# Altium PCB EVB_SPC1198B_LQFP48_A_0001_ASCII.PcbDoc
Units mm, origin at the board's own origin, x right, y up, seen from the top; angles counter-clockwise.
Board outline 65.1 x 66.6 mm, 2 copper layers (Top Layer, Bottom Layer); 51 components, 65 nets, 202 pads, 46 vias.
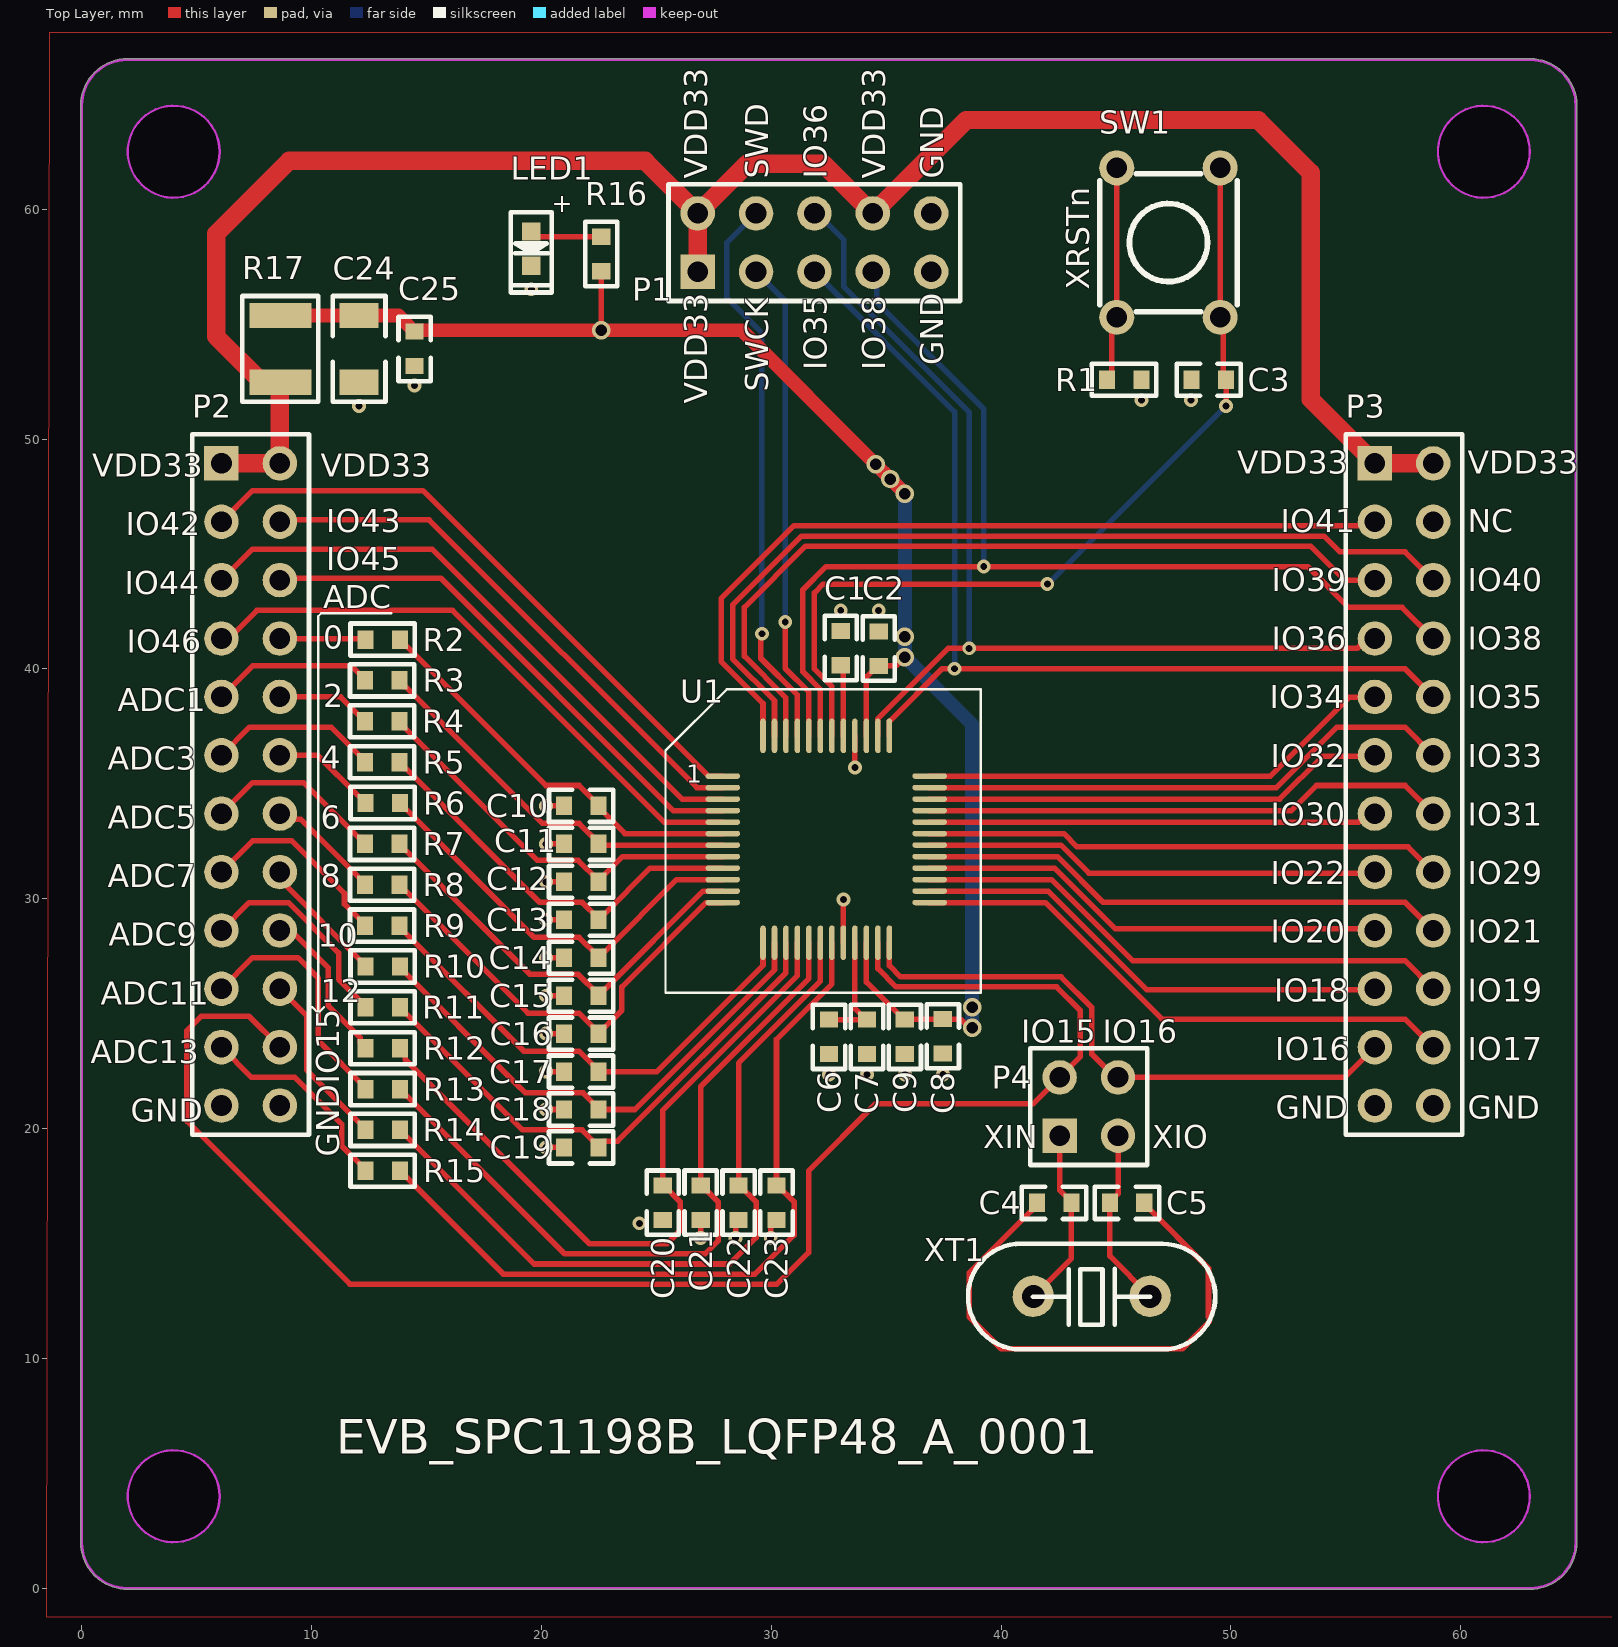
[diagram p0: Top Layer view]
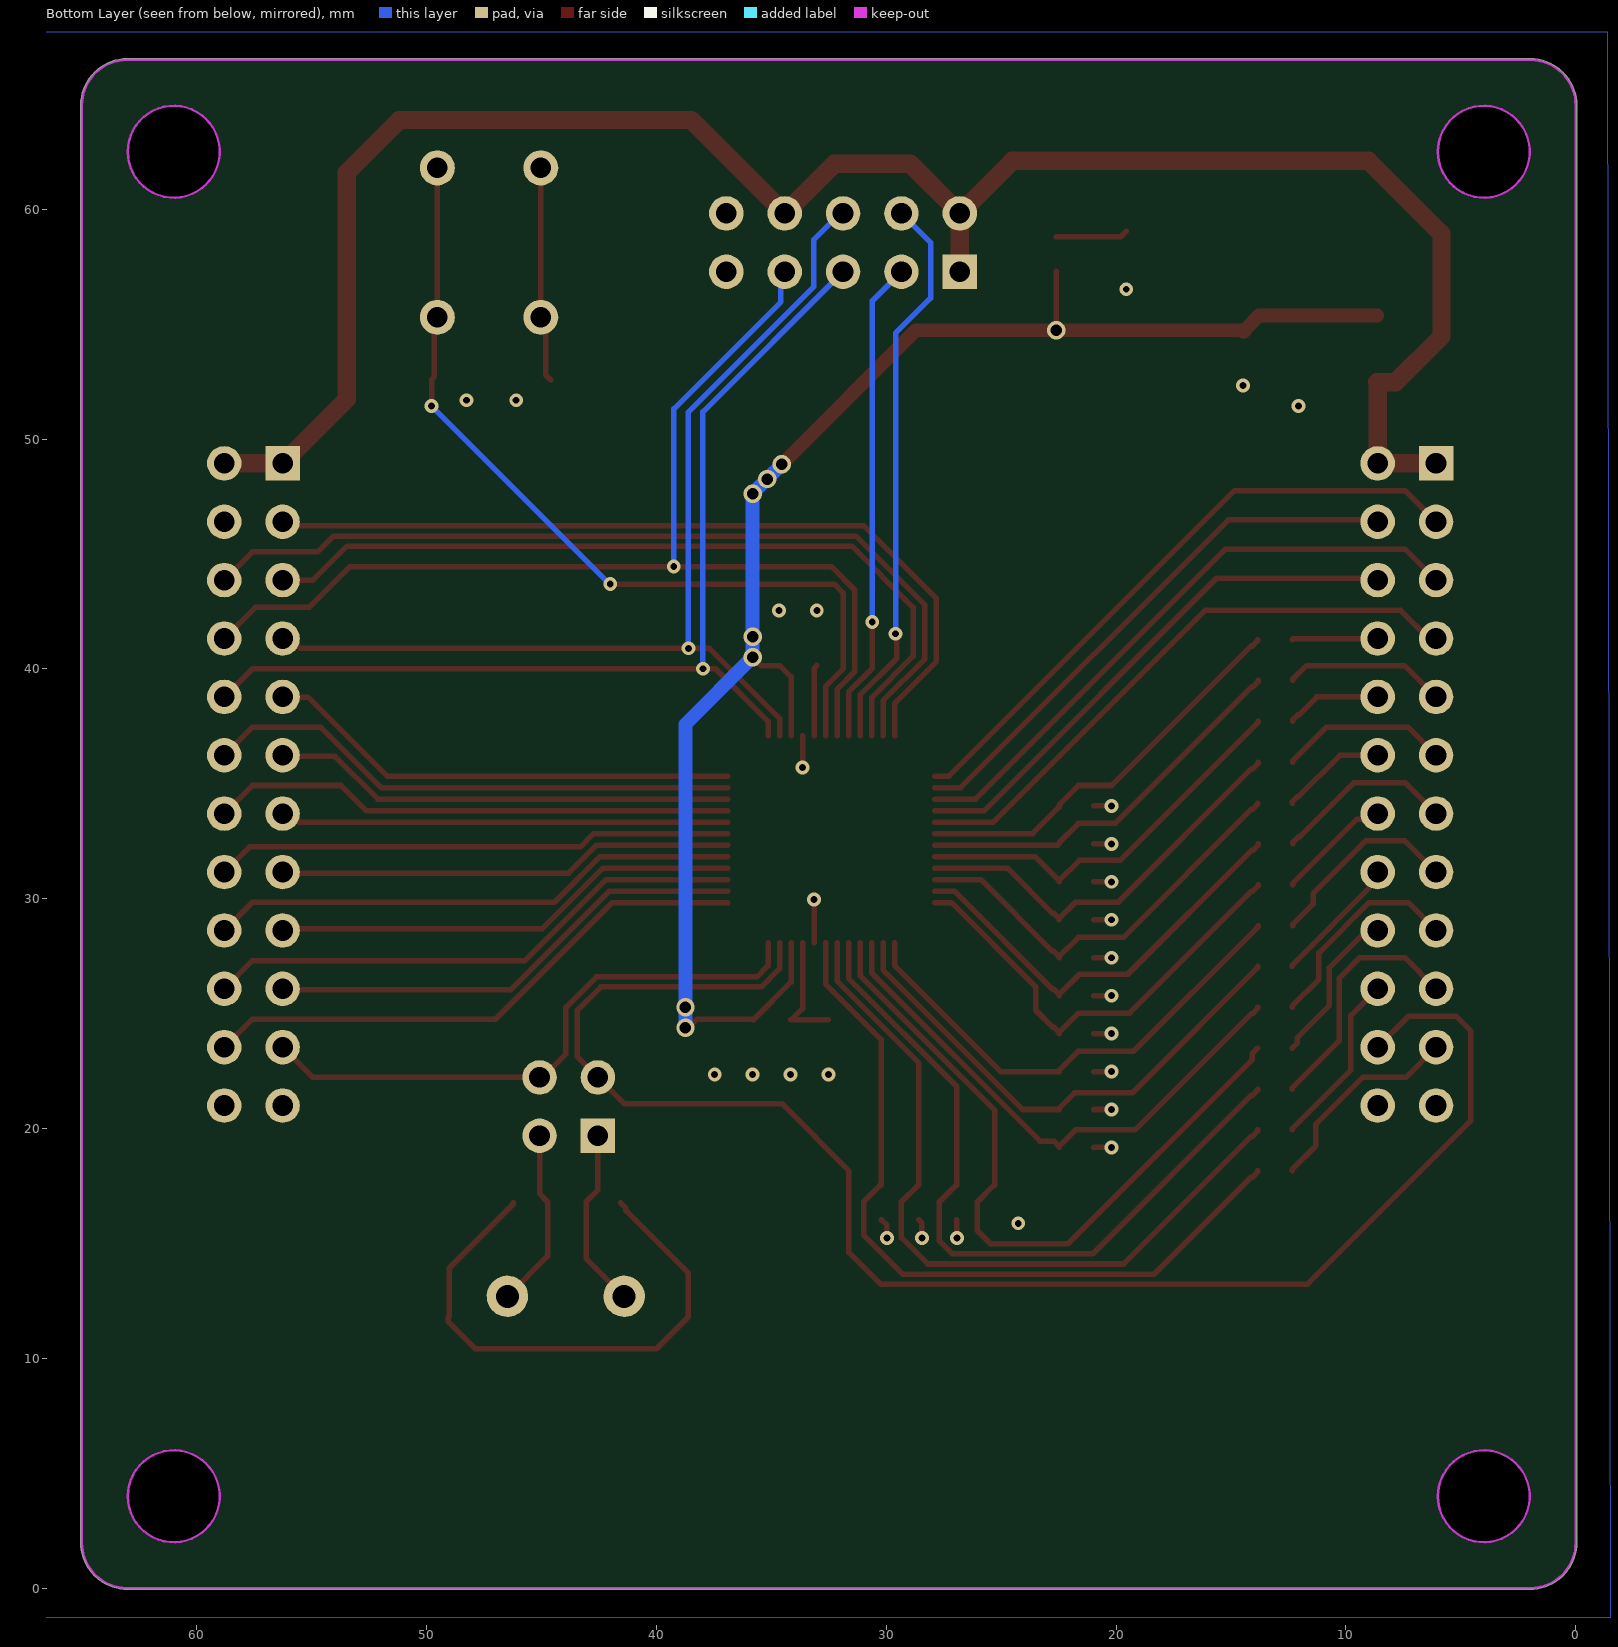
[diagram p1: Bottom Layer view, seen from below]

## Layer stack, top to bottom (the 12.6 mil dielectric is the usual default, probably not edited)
Top Solder: solder mask 0.0102, Solder Resist, Dk 3.5
Top Layer: signal copper 0.0356
Dielectric 1: dielectric 0.32, FR-4, Dk 4.8
Bottom Layer: signal copper 0.0356
Bottom Solder: solder mask 0.0102, Solder Resist, Dk 3.5

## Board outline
-0.05,2 cw(c0,2) -0.048,2.016 cw(c0,2.032) -0.05,2.032 -0.05,64.516 cw(c0,64.516) -0.05,64.519 cw(c2,64.5) 1.981,66.55 cw(c1.984,66.5) 1.984,66.55 63.04,66.55 cw(c63.04,66.5) 63.047,66.55 cw(c63,64.5) 65.05,64.547 cw(c65,64.54) 65.05,64.54 65.05,2.008 cw(c65,2.008) 65.05,2.004 cw(c65,2) 65.05,2 cw(c63,2) 63,-0.05 cw(c63,0) 62.996,-0.05 cw(c62.992,0) 62.992,-0.05 2.032,-0.05 cw(c2.032,0) 2.016,-0.048 cw(c2,0) 2,-0.05 cw(c2,2)

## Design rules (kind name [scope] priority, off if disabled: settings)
AssemblyTestPointUsage [All] p0: scope1count=1 scope1_0_kind=Board scope1_0_value=Board scope2count=1 scope2_0_kind=Board scope2_0_value=Board commentlength=0
AssemblyTestpoint [All] p0: scope1count=1 scope1_0_kind=Board scope1_0_value=Board scope2count=1 scope2_0_kind=Board scope2_0_value=Board commentlength=0
Clearance [All] p0: scope1count=1 scope1_0_kind=Board scope1_0_value=Board scope2count=1 scope2_0_kind=Board scope2_0_value=Board commentlength=0 gap=0.2
Clearance [All] p1: gap=0.2 ignorepadtopadclearanceinfootprint=FALSE except(0: Arc-Hole Track-Hole SMDPad-Hole THPad-Hole Via-Hole Fill-Hole Poly-Hole Region-Hole Text-Hole)
ComponentClearance [All] p0: scope1count=1 scope1_0_kind=Board scope1_0_value=Board scope2count=1 scope2_0_kind=Board scope2_0_value=Board commentlength=0 gap=0.254 collisioncheckmode=3
DiffPairsRouting [All] p0: scope1count=1 scope1_0_kind=Board scope1_0_value=Board scope2count=1 scope2_0_kind=Board scope2_0_value=Board commentlength=0
FabricationTestPointUsage [All] p0: scope1count=1 scope1_0_kind=Board scope1_0_value=Board scope2count=1 scope2_0_kind=Board scope2_0_value=Board commentlength=0 valid=0 allowmultiple=FALSE
FabricationTestpoint [All] p0: scope1count=1 scope1_0_kind=Board scope1_0_value=Board scope2count=1 scope2_0_kind=Board scope2_0_value=Board commentlength=0 side=3 testpointundercomponent=TRUE minsize=1.016 maxsize=2.54 preferedsize=1.524 minholesize=0 maxholesize=1.016 preferedholesize=0.813 testpointgrid=0.025
FanoutControl Fanout_BGA [All] p0 off: scope1count=1 scope1_0_kind=Board scope1_0_value=Board scope2count=1 scope2_0_kind=Board scope2_0_value=Board commentlength=69 // Protel DXP Scope 1 Expression Was: IsBGA   Fanout_BGA (Default Rule)
FanoutControl Fanout_LCC [All] p0 off: scope1count=1 scope1_0_kind=Board scope1_0_value=Board scope2count=1 scope2_0_kind=Board scope2_0_value=Board commentlength=69 // Protel DXP Scope 1 Expression Was: IsLCC   Fanout_LCC (Default Rule)
FanoutControl Fanout_SOIC [All] p0 off: scope1count=1 scope1_0_kind=Board scope1_0_value=Board scope2count=1 scope2_0_kind=Board scope2_0_value=Board commentlength=71 // Protel DXP Scope 1 Expression Was: IsSOIC   Fanout_SOIC (Default Rule)
FanoutControl Fanout_Small [All] p0 off: scope1count=1 scope1_0_kind=Board scope1_0_value=Board scope2count=1 scope2_0_kind=Board scope2_0_value=Board commentlength=84 // Protel DXP Scope 1 Expression Was: (CompPinCount < 5)   Fanout_Small (Default Rule)
FanoutControl Fanout_Default [All] p0: scope1count=1 scope1_0_kind=Board scope1_0_value=Board scope2count=1 scope2_0_kind=Board scope2_0_value=Board commentlength=30 // Fanout_Default (Default Rule)
Height [All] p0: scope1count=1 scope1_0_kind=Board scope1_0_value=Board scope2count=1 scope2_0_kind=Board scope2_0_value=Board commentlength=0
HoleSize [All] p0: scope1count=1 scope1_0_kind=Board scope1_0_value=Board scope2count=1 scope2_0_kind=Board scope2_0_value=Board commentlength=0 absolutevalues=TRUE maxlimit=2.54 minlimit=0.025 maxpercent=80.000 minpercent=20.000
HoleToHoleClearance [All] p0: scope1count=1 scope1_0_kind=Board scope1_0_value=Board scope2count=1 scope2_0_kind=Board scope2_0_value=Board commentlength=0
LayerPairs [All] p0: scope1count=1 scope1_0_kind=Board scope1_0_value=Board scope2count=1 scope2_0_kind=Board scope2_0_value=Board commentlength=0 enforce=TRUE
MinimumSolderMaskSliver [All] p0: scope1count=1 scope1_0_kind=Board scope1_0_value=Board scope2count=1 scope2_0_kind=Board scope2_0_value=Board commentlength=0
NetAntennae [All] p0: scope1count=1 scope1_0_kind=Board scope1_0_value=Board scope2count=1 scope2_0_kind=Board scope2_0_value=Board commentlength=0
PasteMaskExpansion [All] p0: scope1count=1 scope1_0_kind=Board scope1_0_value=Board scope2count=1 scope2_0_kind=Board scope2_0_value=Board commentlength=0 expansion=0
PlaneClearance [All] p0: scope1count=1 scope1_0_kind=Board scope1_0_value=Board scope2count=1 scope2_0_kind=Board scope2_0_value=Board commentlength=0 clearance=0.508
PlaneConnect [All] p0: scope1count=1 scope1_0_kind=Board scope1_0_value=Board scope2count=1 scope2_0_kind=Board scope2_0_value=Board commentlength=0 planeconnectstyle=Direct reliefexpansion=0.508 reliefentries=4 reliefconductorwidth=0.254 reliefairgap=0.254
PlaneConnect [All] p1: planeconnectstyle=Direct reliefexpansion=0.508 reliefentries=4 reliefconductorwidth=0.254 reliefairgap=0.254
PolygonConnect [All] p0: scope1count=1 scope1_0_kind=Board scope1_0_value=Board scope2count=1 scope2_0_kind=Board scope2_0_value=Board commentlength=0 connectstyle=Direct reliefconductorwidth=0.254 reliefentries=4 polygonreliefangle="90 Angle"
PolygonConnect [All] p1: connectstyle=Direct reliefconductorwidth=0.254 reliefentries=4 polygonreliefangle="90 Angle" airgapwidth=0.254
RoutingCorners [All] p0: scope1count=1 scope1_0_kind=Board scope1_0_value=Board scope2count=1 scope2_0_kind=Board scope2_0_value=Board commentlength=0 cornerstyle=45-Degree minsetback=2.54 maxsetback=2.54
RoutingLayers [All] p0: scope1count=1 scope1_0_kind=Board scope1_0_value=Board scope2count=1 scope2_0_kind=Board scope2_0_value=Board commentlength=0 top layer=Automatic bottom layer=Automatic
RoutingPriority [All] p0: scope1count=1 scope1_0_kind=Board scope1_0_value=Board scope2count=1 scope2_0_kind=Board scope2_0_value=Board commentlength=0
RoutingTopology [All] p0: scope1count=1 scope1_0_kind=Board scope1_0_value=Board scope2count=1 scope2_0_kind=Board scope2_0_value=Board commentlength=0 topology=Shortest
RoutingVias [All] p0: scope1count=1 scope1_0_kind=Board scope1_0_value=Board scope2count=1 scope2_0_kind=Board scope2_0_value=Board commentlength=0 holewidth=0.711 width=1.27 viastyle="Through Hole" minholewidth=0.711 minwidth=1.27 maxholewidth=0.711 maxwidth=1.27
RoutingVias [All] p1: holewidth=0.711 width=1.27 viastyle="Through Hole" minholewidth=0.711 minwidth=1.27 maxholewidth=0.711 maxwidth=1.27
ShortCircuit [All] p0: scope1count=1 scope1_0_kind=Board scope1_0_value=Board scope2count=1 scope2_0_kind=Board scope2_0_value=Board commentlength=0 allowed=FALSE
SilkToBoardRegionClearance [All] p0: scope1count=1 scope1_0_kind=Board scope1_0_value=Board scope2count=1 scope2_0_kind=Board scope2_0_value=Board commentlength=0
SilkToSilkClearance [All] p0: scope1count=1 scope1_0_kind=Board scope1_0_value=Board scope2count=1 scope2_0_kind=Board scope2_0_value=Board commentlength=0
SilkToSolderMaskClearance [All] p0 off: scope1count=1 scope1_0_kind=Board scope1_0_value=Board scope2count=1 scope2_0_kind=Board scope2_0_value=Board commentlength=44 // Protel DXP Scope 1 Expression Was: IsPad
SolderMaskExpansion [All] p0: scope1count=1 scope1_0_kind=Board scope1_0_value=Board scope2count=1 scope2_0_kind=Board scope2_0_value=Board commentlength=0 expansion=0.102
SolderMaskExpansion [All] p1: expansion=0.102 istentingtop=FALSE
UnRoutedNet [All] p0: scope1count=1 scope1_0_kind=Board scope1_0_value=Board scope2count=1 scope2_0_kind=Board scope2_0_value=Board commentlength=0
UnpouredPolygon [All] p0: scope1count=1 scope1_0_kind=Board scope1_0_value=Board scope2count=1 scope2_0_kind=Board scope2_0_value=Board commentlength=0
Width [All] p0: scope1count=1 scope1_0_kind=Board scope1_0_value=Board scope2count=1 scope2_0_kind=Board scope2_0_value=Board commentlength=0 maxlimit=4 minlimit=0.15 preferedwidth=0.254
Width [All] p1: maxlimit=4 minlimit=0.15 preferedwidth=0.254 minimp=50.000000 maximp=50.000000 favimp=50.000000
29 further rules are at their usual default settings.

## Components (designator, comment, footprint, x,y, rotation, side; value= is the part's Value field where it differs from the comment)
C1 "100nF" 0603C 33.02,40.156 r90 top
C2 "100nF" 0603C 34.671,41.632 r270 top
C3 "100nF" 0603C 48.284,52.578 r0 top
C4 "20pF" 0603C 41.553,16.764 r0 top
C5 "20pF" 0603C 46.228,16.764 r180 top
C6 "2.2uF" 0603C 32.512,23.241 r90 top
C7 "100nF" 0603C 34.163,23.241 r90 top
C8 "2.2uF" 0603C 37.465,23.265 r90 top
C9 "100nF" 0603C 35.814,23.241 r90 top
C10 "100pF" 0603C 22.479,34.036 r180 top
C11 "100pF" 0603C 22.479,32.385 r180 top
C12 "100pF" 0603C 22.479,30.734 r180 top
C13 "100pF" 0603C 22.479,29.083 r180 top
C14 "100pF" 0603C 22.479,27.432 r180 top
C15 "100pF" 0603C 22.479,25.781 r180 top
C16 "100pF" 0603C 22.479,24.13 r180 top
C17 "100pF" 0603C 22.479,22.479 r180 top
C18 "100pF" 0603C 22.479,20.828 r180 top
C19 "100pF" 0603C 22.479,19.177 r180 top
C20 "100pF" 0603C 25.273,17.526 r270 top
C21 "100pF" 0603C 26.924,17.526 r270 top
C22 "100pF" 0603C 28.575,17.526 r270 top
C23 "100pF" 0603C 30.226,17.526 r270 top
C24 "47uF" 1206C 12.065,52.472 r90 top
C25 "100nF" 0603C 14.478,53.172 r90 top
LED1 "" LED0603 19.558,59.031 r270 top
P1 "Header 5X2" HDR2X5 26.797,57.277 r0 top
P2 "Header 12X2" HDR2X12 6.077,48.94 r270 top locked
P3 "Header 12X2" HDR2X12 56.261,48.94 r270 top locked
P4 "Header 2X2" HDR2X2 42.545,19.685 r0 top
R1 "2K" 0603R 44.601,52.578 r0 top
R2 "100R" 0603R 13.843,41.275 r180 top
R3 "100R" 0603R 13.819,39.497 r180 top
R4 "100R" 0603R 13.819,37.719 r180 top
R5 "100R" 0603R 13.819,35.941 r180 top
R6 "100R" 0603R 13.843,34.163 r180 top
R7 "100R" 0603R 13.819,32.385 r180 top
R8 "100R" 0603R 13.819,30.607 r180 top
R9 "100R" 0603R 13.819,28.829 r180 top
R10 "100R" 0603R 13.843,27.051 r180 top
R11 "100R" 0603R 13.843,25.273 r180 top
R12 "100R" 0603R 13.843,23.495 r180 top
R13 "100R" 0603R 13.843,21.717 r180 top
R14 "100R" 0603R 13.843,19.939 r180 top
R15 "100R" 0603R 13.843,18.161 r180 top
R16 "3.3K" 0603R 22.606,57.301 r90 top
R17 "0.1R" 1210R 8.636,55.372 r270 top
SW1 "插件按键6*6*5" Key_6*6 49.53,61.797 r0 top
U1 "SPC1198B_LQFP64" LQFP-48-0.5 27.889,35.334 r0 top locked
XT1 "32MHz" XT-HI 43.942,12.7 r0 top
? "Comment" 旋智标识8*3.5 10.922,8.89 r0 top

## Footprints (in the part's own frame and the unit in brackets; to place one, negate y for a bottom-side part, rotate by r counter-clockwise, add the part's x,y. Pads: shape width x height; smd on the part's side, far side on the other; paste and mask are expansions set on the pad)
0603C [mm]
  rect 0.7x0.8 smd: 1(0,0) 2(1.5,0)
  silkscreen extent -0.65,-0.7 2.15,0.7
0603R [mm]
  rect 0.7x0.8 smd: 1(0,0) 2(1.5,0)
  silkscreen extent -0.65,-0.7 2.15,0.7
1206C [mm]
  rect 1.1x1.7 smd: 1(0,0) 2(2.9,0)
  silkscreen extent -0.85,-1.15 3.75,1.15
1210R [mm]
  rect 1.1x2.7 smd: 1(0,0) 2(2.9,0)
  silkscreen extent -0.85,-1.65 3.75,1.65
HDR2X2 [mm] "Connector; Header; 2x2 Position"
  rect 1.5x1.5 hole 0.9: 1(0,0)
  round 1.5 hole 0.9: 2(0,2.54) 3(2.54,0) 4(2.54,2.54)
  silkscreen extent -1.27,-1.27 3.81,3.81
HDR2X5 [mm] "Connector; Header; 5x2 Position"
  rect 1.5x1.5 hole 0.9: 1(0,0)
  round 1.5 hole 0.9: 2(0,2.54) 3(2.54,0) 4(2.54,2.54) 5(5.08,0) 6(5.08,2.54) 7(7.62,0) 8(7.62,2.54) 9(10.16,0) 10(10.16,2.54)
  silkscreen extent -1.27,-1.27 11.43,3.81
HDR2X12 [mm] "Connector; Header; 12x2 Position"
  rect 1.5x1.5 hole 0.9: 1(0,0)
  round 1.5 hole 0.9: 2(0,2.54) 3(2.54,0) 4(2.54,2.54) 5(5.08,0) 6(5.08,2.54) 7(7.62,0) 8(7.62,2.54) 9(10.16,0) 10(10.16,2.54) 11(12.7,0) 12(12.7,2.54) 13(15.24,0) 14(15.24,2.54) 15(17.78,0) 16(17.78,2.54) 17(20.32,0) 18(20.32,2.54) 19(22.86,0) 20(22.86,2.54) 21(25.4,0) 22(25.4,2.54) 23(27.94,0) 24(27.94,2.54)
  silkscreen extent -1.27,-1.27 29.21,3.81
Key_6*6 [mil]
  round 60 hole 35: 1(0,-255.9) 1(0,0) 2(-177.16,-255.9) 2(-177.16,0)
  silkscreen extent -207,-246 30,-10
LED0603 [mm]
  rect 0.8x0.8 smd: A(0,0) K(1.5,0)
  silkscreen extent -0.84,-0.89 2.66,0.89
LQFP-48-0.5 [mm] "P-0.5,7*7mm"
  oval 1.5x0.24 smd: 1(0,0) 2(0,-0.5) 3(0,-1) 4(0,-1.5) 5(0,-2) 6(0,-2.5) 7(0,-3) 8(0,-3.5) 9(0,-4) 10(0,-4.5) 11(0,-5) 12(0,-5.5) 25(9,-5.5) 26(9,-5) 27(9,-4.5) 28(9,-4) 29(9,-3.5) 30(9,-3) 31(9,-2.5) 32(9,-2) 33(9,-1.5) 34(9,-1) 35(9,-0.5) 36(9,0)
  oval 0.24x1.5 smd: 13(1.75,-7.25) 14(2.25,-7.25) 15(2.75,-7.25) 16(3.25,-7.25) 17(3.75,-7.25) 18(4.25,-7.25) 19(4.75,-7.25) 20(5.25,-7.25) 21(5.75,-7.25) 22(6.25,-7.25) 23(6.75,-7.25) 24(7.25,-7.25) 37(7.25,1.75) 38(6.75,1.75) 39(6.25,1.75) 40(5.75,1.75) 41(5.25,1.75) 42(4.75,1.75) 43(4.25,1.75) 44(3.75,1.75) 45(3.25,1.75) 46(2.75,1.75) 47(2.25,1.75) 48(1.75,1.75)
XT-HI [mm]
  round 1.8 hole 1: 1(-2.54,0) 2(2.54,0)
  silkscreen extent -5.38,-2.31 5.38,2.29
旋智标识8*3.5 [mm]

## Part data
C1 C2 C3 C4 C5 C6 C7 C8 C9 C10 C11 C12 C13 C14 C15 C16 C17 C18 C19 C20 C21 C22 C23 C24 C25: library part Capacitor, "无极性电容"
LED1: library part LED, "发光二极管"
P1: "Header, 5-Pin, Dual row"
P2 P3: "Header, 12-Pin, Dual row"
P4: "Header, 2-Pin, Dual row"
R1 R2 R3 R4 R5 R6 R7 R8 R9 R10 R11 R12 R13 R14 R15 R16 R17: library part Resistance, "电阻"
SW1: library part SW-PB, "Switch"
XT1: library part CRYSTAL-2P

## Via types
v1: diameter 0.6, hole 0.3, Top Layer to Bottom Layer, tented both sides, 34 vias
v2: diameter 0.8, hole 0.5, Top Layer to Bottom Layer, tented both sides, 8 vias
v3: diameter 4, hole 4, Top Layer to Bottom Layer, tented both sides, 4 vias

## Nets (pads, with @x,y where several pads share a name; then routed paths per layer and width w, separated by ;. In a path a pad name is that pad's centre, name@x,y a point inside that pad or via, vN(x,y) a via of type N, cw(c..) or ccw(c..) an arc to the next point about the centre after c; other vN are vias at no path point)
ADC0: P2.8 R2.2 | length 3.7
  Top Layer w0.24: P2.8 12.298,41.32 R2.2
ADC1: P2.9 R3.2 | length 7.1
  Top Layer w0.24: P2.9 7.429,40.132 11.734,40.132 12.319,39.547 R3.2
ADC2: P2.10 R4.2 | length 4.2
  Top Layer w0.24: P2.10 11.258,38.78 12.039,37.999 12.089,37.999 12.319,37.769 R4.2
ADC3: P2.11 R5.2 | length 7.4
  Top Layer w0.24: P2.11 7.302,37.465 10.845,37.465 12.319,35.991 R5.2
ADC4: P2.12 R6.2 | length 4.6
  Top Layer w0.24: P2.12 10.266,36.24 12.063,34.443 12.113,34.443 12.343,34.213 R6.2
ADC5: P2.13 R7.2 | length 7.9
  Top Layer w0.24: P2.13 7.429,35.052 9.652,35.052 12.039,32.665 12.089,32.665 12.319,32.435 R7.2
ADC6: P2.14 R8.2 | length 5
  Top Layer w0.24: P2.14 8.858,33.459 9.517,33.459 12.319,30.657 R8.2
ADC7: P2.15 R9.2 | length 8.6
  Top Layer w0.24: P2.15 7.429,32.512 9.144,32.512 11.43,30.226 11.43,29.768 12.319,28.879 R9.2
ADC8: P2.16 R10.2 | length 5.7
  Top Layer w0.24: P2.16 8.617,30.827 12.343,27.101 R10.2
ADC9: P2.17 R11.2 | length 9.4
  Top Layer w0.24: P2.17 7.282,29.825 8.997,29.825 11.176,27.646 11.176,26.49 12.343,25.323 R11.2
ADC10: P2.18 R12.2 | length 7
  Top Layer w0.24: P2.18 8.858,28.379 9.34,28.379 10.727,26.992 10.727,25.341 12.113,23.955 12.113,23.725 R12.2
ADC11: P2.19 R13.2 | length 10.8
  Top Layer w0.24: P2.19 7.429,27.432 9.398,27.432 10.287,26.543 10.287,23.823 12.343,21.767 R13.2
ADC12: P2.20 R14.2 | length 7.7
  Top Layer w0.24: P2.20 9.779,24.918 9.779,22.553 12.343,19.989 R14.2
ADC13: P2.21 R15.2 | length 9.1
  Top Layer w0.24: P2.21 7.392,22.225 9.271,22.225 11.303,20.193 11.303,19.251 12.343,18.211 R15.2
DVDD: C2.2 C8.2 C9.2 C24.2 C25.2 R16.1 R17.1 U1.22 U1.39 | length 71
  Top Layer w0.24: v2(22.606,54.737) R16.1 ; U1.22 34.139,26.366 35.764,24.741 C9.2 35.826,24.753 37.453,24.753 C8.2 38.225,24.765 38.606,24.384 v2(38.735,24.384) ; U1.39 34.139,39.65 34.621,40.132 C2.2 35.415,40.132 35.796,40.513 v2(35.814,40.513)
  Top Layer w0.6: R17.1 C24.2 13.778,55.372 14.378,54.772 14.378,54.722 14.428,54.672 C25.2 14.543,54.737 v2(22.606,54.737) 28.702,54.737 v2(34.544,48.895) v2(35.179,48.26) v2(35.814,47.625)
  Bottom Layer w0.6: v2(34.544,48.895) v2(35.179,48.26) v2(35.814,47.625) v2(35.814,41.402) v2(35.814,40.513) 38.735,37.592 v2(38.735,25.273) v2(38.735,24.384)
GND: C1.2 C2.1 C3.1 C4.1 C5.1 C6.1 C7.1 C8.1 C9.1 C10.2 C11.2 C12.2 C13.2 C14.2 C15.2 C16.2 C17.2 C18.2 C19.2 C20.2 C21.2 C22.2 C23.2 C24.1 C25.1 LED1.K P1.9 P1.10 P2.23 P2.24 P3.23 P3.24 R1.2 U1.20 U1.40 | length 37.7
  Top Layer w0.24: v1(20.193,19.177) C19.2 ; v1(20.193,20.828) C18.2 ; v1(20.193,22.479) C17.2 ; v1(20.193,24.13) C16.2 ; v1(20.193,25.781) C15.2 ; v1(20.193,27.432) C14.2 ; v1(20.193,29.083) C13.2 ; v1(20.193,30.734) C12.2 ; v1(20.193,32.385) C11.2 ; v1(20.193,34.036) C10.2 ; v1(26.924,15.24) C21.2 ; v1(28.448,15.24) 28.448,15.899 C22.2 ; v1(29.972,15.24) 29.972,15.796 30.202,16.026 C23.2 ; U1.20 v1(33.139,29.964) v1@33.147,29.972 ; U1.40 v1(33.639,35.703) v1@33.655,35.687 ; C4.1 41.323,16.534 41.323,16.431 38.608,13.716 38.608,11.811 40.005,10.414 47.879,10.414 49.05,11.585 49.05,11.783 49.022,11.811 49.022,13.92 46.228,16.714 C5.1
  other v1: 24.257,15.875 32.512,22.352 34.163,22.352 35.814,22.352 37.465,22.352 33.02,42.545 34.671,42.545 12.065,51.435 46.101,51.689 48.26,51.689 14.478,52.324 19.558,56.515
GPIO0: C10.1 R2.1 U1.6 | length 17.6
  Top Layer w0.24: R2.1 13.843,41.225 14.073,40.995 14.123,40.995 20.193,34.925 21.64,34.925 22.479,34.086 C10.1 22.479,33.986 23.631,32.834 U1.6
GPIO1: C11.1 R3.1 U1.7 | length 17.1
  Top Layer w0.24: R3.1 13.819,39.447 14.049,39.217 14.099,39.217 20.042,33.274 21.64,33.274 22.479,32.435 C11.1 22.53,32.334 U1.7
GPIO2: C12.1 R4.1 U1.8 | length 17.5
  Top Layer w0.24: R4.1 13.819,37.669 14.049,37.439 19.823,31.665 21.598,31.665 C12.1@22.479,30.784 ; C12.1 C12.1@22.479,30.784 ; U1.8 23.529,31.834 C12.1@22.479,30.784
GPIO3: C13.1 R5.1 U1.9 | length 17.9
  Top Layer w0.24: R5.1 13.819,35.891 14.049,35.661 14.099,35.661 19.915,29.845 21.767,29.845 C13.1@22.479,29.133 ; C13.1 C13.1@22.479,29.133 ; U1.9 24.73,31.334 22.759,29.363 22.709,29.363 C13.1@22.479,29.133
GPIO4: C14.1 R6.1 U1.10 | length 18.3
  Top Layer w0.24: R6.1 13.843,34.113 14.073,33.883 14.123,33.883 19.685,28.321 21.64,28.321 C14.1@22.479,27.482 ; C14.1 C14.1@22.479,27.482 ; U1.10 25.881,30.834 22.759,27.712 22.709,27.712 C14.1@22.479,27.482
GPIO5: C15.1 R7.1 U1.11 | length 18.7
  Top Layer w0.24: R7.1 13.819,32.335 14.049,32.105 14.099,32.105 19.492,26.712 21.598,26.712 C15.1@22.479,25.831 ; C15.1 C15.1@22.479,25.831 ; U1.11 27.032,30.334 22.759,26.061 22.709,26.061 C15.1@22.479,25.831
GPIO6: C16.1 R8.1 U1.12 | length 19.7
  Top Layer w0.24: R8.1 13.819,30.557 14.049,30.327 14.099,30.327 19.407,25.019 21.64,25.019 C16.1@22.479,24.18 ; C16.1 C16.1@22.479,24.18 ; U1.12 27.167,29.834 23.495,26.162 23.495,25.146 22.759,24.41 22.709,24.41 C16.1@22.479,24.18
GPIO7: C17.1 R9.1 U1.13 | length 21.4
  Top Layer w0.24: R9.1 13.819,28.779 14.049,28.549 19.23,23.368 21.64,23.368 22.479,22.529 C17.1 25.019,22.479 29.639,27.099 U1.13
GPIO8: C18.1 R10.1 U1.14 | length 22.6
  Top Layer w0.24: R10.1 13.843,27.001 18.873,21.971 19.296,21.548 21.809,21.548 22.479,20.878 C18.1 24.067,20.828 30.139,26.9 U1.14
GPIO9: C19.1 R11.1 U1.15 | length 23.8
  Top Layer w0.24: R11.1 13.843,25.223 14.073,24.993 14.123,24.993 19.177,19.939 21.767,19.939 C19.1@22.479,19.227 ; C19.1 C19.1@22.479,19.227 ; U1.15 30.639,26.778 23.318,19.457 22.709,19.457 C19.1@22.479,19.227
GPIO10: C20.1 R12.1 U1.16 | length 31.4
  Top Layer w0.24: R12.1 14.073,23.265 14.073,23.011 22.098,14.986 25.468,14.986 26.035,15.553 26.035,16.814 25.323,17.526 C20.1 25.273,20.79 31.139,26.656 U1.16
GPIO11: C21.1 R13.1 U1.17 | length 32.3
  Top Layer w0.24: R13.1 13.843,21.667 14.073,21.437 14.123,21.437 21.014,14.546 27.119,14.546 27.686,15.113 27.686,16.814 26.974,17.526 C21.1 26.924,21.819 31.639,26.534 U1.17
GPIO12: C22.1 R14.1 U1.18 | length 33.1
  Top Layer w0.24: R14.1 13.843,19.889 14.073,19.659 14.123,19.659 19.676,14.106 28.189,14.106 29.337,15.254 29.337,16.814 28.625,17.526 C22.1 28.575,22.847 32.139,26.411 U1.18
GPIO13: C23.1 R15.1 U1.19 | length 33.8
  Top Layer w0.24: R15.1 13.843,18.111 14.073,17.881 14.123,17.881 18.338,13.666 29.287,13.666 30.988,15.367 30.988,16.814 30.276,17.526 C23.1 30.226,23.876 32.639,26.289 U1.19
GPIO15: P2.22 P4.2 U1.23 | length 69.5
  Top Layer w0.24: P2.22 7.265,24.892 5.207,24.892 4.572,24.257 4.572,20.32 11.666,13.226 30.244,13.226 31.623,14.605 31.623,18.161 34.544,21.082 41.402,21.082 43.434,23.114 43.434,25.146 42.418,26.162 35.433,26.162 34.639,26.956 U1.23
GPIO16: P3.21 P4.4 U1.24 | length 25.9
  Top Layer w0.24: U1.24 35.139,27.091 35.628,26.602 42.613,26.602 43.942,25.273 43.942,23.241 44.958,22.225 P4.4 54.946,22.225 P3.21
GPIO17: P3.22 U1.25 | length 24.5
  Top Layer w0.24: U1.25 41.921,29.834 46.99,24.765 57.576,24.765 P3.22
GPIO18: P3.19 U1.26 | length 21.2
  Top Layer w0.24: U1.26 42.043,30.334 46.342,26.035 56.216,26.035 P3.19
GPIO19: P3.20 U1.27 | length 23.9
  Top Layer w0.24: U1.27 42.191,30.834 45.72,27.305 57.576,27.305 P3.20
GPIO20: P3.17 U1.28 | length 20.5
  Top Layer w0.24: U1.28 42.326,31.334 44.958,28.702 56.179,28.702 P3.17
GPIO21: P3.18 U1.29 | length 23.2
  Top Layer w0.24: U1.29 42.448,31.834 44.437,29.845 57.576,29.845 P3.18
GPIO22: P3.15 U1.30 | length 19.9
  Top Layer w0.24: U1.30 42.596,32.334 43.815,31.115 56.216,31.115 P3.15
GPIO29: P3.16 U1.31 | length 22.6
  Top Layer w0.24: U1.31 42.731,32.834 43.307,32.258 57.703,32.258 P3.16
GPIO30: P3.13 U1.32 | length 19.5
  Top Layer w0.24: U1.32 55.554,33.334 55.92,33.7 P3.13
GPIO31: P3.14 U1.33 | length 22.9
  Top Layer w0.24: U1.33 52.63,33.834 53.721,34.925 57.576,34.925 P3.14
GPIO32: P3.11 U1.34 | length 20.2
  Top Layer w0.24: U1.34 52.114,34.334 53.975,36.195 56.216,36.195 P3.11
GPIO33: P3.12 U1.35 | length 23.5
  Top Layer w0.24: U1.35 51.979,34.834 54.61,37.465 57.576,37.465 P3.12
GPIO34: P3.9 U1.36 | length 20.8
  Top Layer w0.24: U1.36 51.717,35.334 55.151,38.768 56.249,38.768 P3.9
GPIO35: P1.5 P3.10 U1.37 | length 45.5
  Top Layer w0.24: U1.37 35.139,37.714 37.43,40.005 v1(37.973,40.005) 57.576,40.005 P3.10
  Bottom Layer w0.24: P1.5 37.973,51.181 v1(37.973,40.005)
GPIO36: P1.6 P3.7 U1.38 | length 45.6
  Top Layer w0.24: U1.38 34.639,37.836 37.697,40.894 v1(38.608,40.894) 55.494,40.894 55.92,41.32 P3.7
  Bottom Layer w0.24: P1.6 32.004,59.817 33.147,58.674 33.147,56.629 38.608,51.168 v1(38.608,40.894)
GPIO38: P1.7 P3.8 U1.43 | length 50.6
  Top Layer w0.24: U1.43 32.139,39.108 31.369,39.878 31.369,43.434 32.385,44.45 v1(39.243,44.45) 53.34,44.45 55.118,42.672 57.449,42.672 P3.8
  Bottom Layer w0.24: P1.7 34.581,57.113 34.581,55.97 39.243,51.308 v1(39.243,44.45)
GPIO39: P3.5 U1.46 | length 35.5
  Top Layer w0.24: U1.46 30.639,38.741 28.829,40.551 28.829,42.672 31.496,45.339 53.467,45.339 54.946,43.86 P3.5
GPIO40: P3.6 U1.47 | length 39
  Top Layer w0.24: U1.47 30.139,38.619 28.321,40.437 28.321,42.786 31.314,45.779 54.043,45.779 54.737,45.085 57.576,45.085 P3.6
GPIO41: P3.3 U1.48 | length 36.6
  Top Layer w0.24: U1.48 29.639,38.497 27.813,40.323 27.813,43.053 30.988,46.228 56.089,46.228 P3.3
GPIO42: P2.3 U1.1 | length 27.5
  Top Layer w0.24: P2.3 7.429,47.752 14.841,47.752 27.259,35.334 U1.1
GPIO43: P2.4 U1.2 | length 24.1
  Top Layer w0.24: P2.4 8.699,46.482 15.113,46.482 26.761,34.834 U1.2
GPIO44: P2.5 U1.3 | length 26.9
  Top Layer w0.24: P2.5 7.429,45.212 15.24,45.212 26.118,34.334 U1.3
GPIO45: P2.6 U1.4 | length 23.5
  Top Layer w0.24: P2.6 8.699,43.942 15.621,43.942 25.729,33.834 U1.4
GPIO46: P2.7 U1.5 | length 26.1
  Top Layer w0.24: P2.7 6.395,41.32 7.62,42.545 16.129,42.545 25.34,33.334 U1.5
NetLED1_A: LED1.A R16.2 | length 3.1
  Top Layer w0.24: LED1.A 19.788,58.801 R16.2
NetR1_1: R1.1 SW1.2 | length 9.4
  Top Layer w0.24: R1.1 44.816,52.793 44.816,55.083 45.03,55.297 SW1.2@45.03,61.797
SWCK: P1.3 U1.44 | length 21.1
  Top Layer w0.24: v1(30.607,42.037) 30.607,40.018 31.639,38.986 U1.44
  Bottom Layer w0.24: P1.3 30.607,56.007 v1(30.607,42.037)
SWD: P1.4 U1.45 | length 24.6
  Top Layer w0.24: v1(29.591,41.529) 29.54,41.478 29.54,40.462 31.139,38.863 U1.45
  Bottom Layer w0.24: P1.4 28.067,58.547 28.067,56.134 29.591,54.61 v1(29.591,41.529)
VCAP12A: C6.2 C7.2 U1.21 | length 5.2
  Top Layer w0.24: C6.2 C7.2@34.113,24.741 ; U1.21 33.639,25.215 C7.2@34.113,24.741 ; C7.2 C7.2@34.113,24.741
VCAP12B: C1.1 U1.41 | length 3.1
  Top Layer w0.24: C1.1 33.139,40.037 U1.41
VDD33: P1.1 P1.2 P1.8 P2.1 P2.2 P3.1 P3.2 R17.2 | length 87.4
  Top Layer w0.8: P2.1 P2.2 8.617,52.453 R17.2 7.836,52.472 5.842,54.466 5.842,58.928 9.017,62.103 24.511,62.103 P1.2 ; P1.1 P1.2 ; P3.2 P3.1 53.467,51.734 53.467,61.595 51.181,63.881 38.481,63.881 P1.8 32.258,61.976 28.956,61.976 P1.2
XIN: C4.2 P4.1 XT1.1 | length 7.9
  Top Layer w0.24: XT1.1 43.053,14.351 C4.2 43.053,16.814 42.545,17.322 P4.1
XIO: C5.2 P4.3 XT1.2 | length 7.9
  Top Layer w0.24: P4.3 45.085,17.171 44.728,16.814 C5.2 44.728,14.454 XT1.2
XRSTn: C3.2 SW1.1 U1.42 | length 38.3
  Top Layer w0.24: U1.42 32.639,39.241 31.877,40.003 31.877,43.307 32.258,43.688 v1(42.009,43.688) ; SW1.1@49.53,61.797 49.53,55.297 49.657,55.17 49.657,52.705 C3.2 v1(49.784,51.435)
  Bottom Layer w0.24: v1(42.009,43.688) 42.037,43.688 v1(49.784,51.435)
pads on no net: P3.4
copper on no net:
  other v3: 4,4 61,4 4,62.5 61,62.5

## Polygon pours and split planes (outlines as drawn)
GND on Top Layer "NONET_L01_P-001" (solid, remove dead copper, pour order 1): -1.397,67.691 67.056,67.691 67.056,-1.27 -1.524,-1.27
no net on Top Layer "NONET_L01_P-001" (solid, pour order 0): -1.397,67.691
GND on Bottom Layer "NONET_L01_P-001" (solid, remove dead copper, pour order 2): -1.397,67.691 67.056,67.691 67.056,-1.27 -1.524,-1.27

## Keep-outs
Keep-Out Layer:
  circle w0.1: c4,4 r2
  circle w0.1: c61,4 r2
  circle w0.1: c61,62.5 r2
  circle w0.1: c4,62.5 r2
  lines w0.1: 0,2 ccw(c2,2) 2,0 ; 0,2.032 0,64.516 ; 0,64.5 cw(c2,64.5) 2,66.5 ; 1.984,66.5 63.04,66.5 ; 2.032,0 62.992,0 ; 63,0 ccw(c63,2) 65,2 ; 63,66.5 cw(c63,64.5) 65,64.5 ; 65,2.008 65,64.54

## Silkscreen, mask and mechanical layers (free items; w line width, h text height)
Top Overlay:
  lines w0.1: 9.906,41.402 9.906,41.783 ; 9.906,43.815 9.906,44.069 ; 10.033,25.273 10.287,25.019 ; 10.541,25.273 10.287,25.019 ; 13.462,42.418 10.414,42.418 10.287,42.291 10.287,25.019 ; 25.4,25.908 39.116,25.908 39.116,39.116 28.067,39.116 25.4,36.449 25.4,25.908
  text "VDD33" at 27.205,61.314 h1 r90
  text "SWD" at 29.872,61.314 h1 r90
  text "IO36" at 32.412,61.314 h1 r90
  text "VDD33" at 34.952,61.314 h1 r90
  text "GND" at 37.492,61.314 h1 r90
  text "XRSTn" at 43.842,56.488 h1 r90
  text "GND" at 37.492,53.211 h1 r90
  text "IO35" at 32.412,53.001 h1 r90
  text "IO38" at 34.952,53.001 h1 r90
  text "SWCK" at 29.872,52.059 h1 r90
  text "VDD33" at 27.205,51.535 h1 r90
  text "VDD33" at 50.265,48.487 h1
  text "VDD33" at 60.298,48.487 h1
  text "VDD33" at 0.449,48.36 h1
  text "VDD33" at 10.387,48.36 h1
  text "IO43" at 10.641,45.947 h1
  text "IO41" at 52.16,45.935 h1
  text "NC" at 60.298,45.935 h1
  text "IO42" at 1.916,45.808 h1
  text "IO45" at 10.641,44.296 h1
  text "IO39" at 51.779,43.384 h1
  text "IO40" at 60.298,43.384 h1
  text "IO44" at 1.868,43.257 h1
  text "ADC" at 10.514,42.645 h1
  text "0" at 10.514,40.867 h1
  text "IO36" at 51.779,40.832 h1
  text "IO38" at 60.298,40.832 h1
  text "IO46" at 1.963,40.705 h1
  text "2" at 10.514,38.327 h1
  text "IO34" at 51.684,38.281 h1
  text "IO35" at 60.298,38.281 h1
  text "ADC1" at 1.559,38.154 h1
  text "IO32" at 51.731,35.729 h1
  text "IO33" at 60.298,35.729 h1
  text "4" at 10.387,35.66 h1
  text "ADC3" at 1.13,35.602 h1
  text "IO30" at 51.731,33.178 h1
  text "IO31" at 60.298,33.178 h1
  text "ADC5" at 1.13,33.051 h1
  text "6" at 10.387,33.051 h1
  text "IO22" at 51.731,30.626 h1
  text "IO29" at 60.298,30.626 h1
  text "ADC7" at 1.13,30.499 h1
  text "8" at 10.387,30.499 h1
  text "IO20" at 51.731,28.075 h1
  text "IO21" at 60.298,28.075 h1
  text "ADC9" at 1.178,27.948 h1
  text "10" at 10.26,27.913 h1
  text "IO18" at 51.888,25.523 h1
  text "IO19" at 60.298,25.523 h1
  text "12" at 10.387,25.5 h1
  text "ADC11" at 0.825,25.396 h1
  text "IO15" at 40.867,23.722 h1
  text "IO16" at 44.423,23.722 h1
  text "IO16" at 51.936,22.972 h1
  text "IO17" at 60.298,22.972 h1
  text "ADC13" at 0.397,22.845 h1
  text "IO15" at 11.203,21.944 h1 r90
  text "GND" at 51.941,20.42 h1
  text "GND" at 60.298,20.42 h1
  text "GND" at 2.125,20.293 h1
  text "XIN" at 39.216,19.15 h1
  text "XIO" at 46.582,19.15 h1
  text "GND" at 11.203,18.769 h1 r90
  text "EVB_SPC1198B_LQFP48_A_0001" at 11.072,5.857 h1.5
Mechanical 1:
  lines w0.1: 0,2 ccw(c2,2) 2,0 ; 0,2.032 0,64.516 ; 0,64.5 cw(c2,64.5) 2,66.5 ; 1.984,66.5 63.04,66.5 ; 2.032,0 62.992,0 ; 63,0 ccw(c63,2) 65,2 ; 63,66.5 cw(c63,64.5) 65,64.5 ; 65,2.008 65,64.54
